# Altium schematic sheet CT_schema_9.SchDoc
size 274 x 160 mm
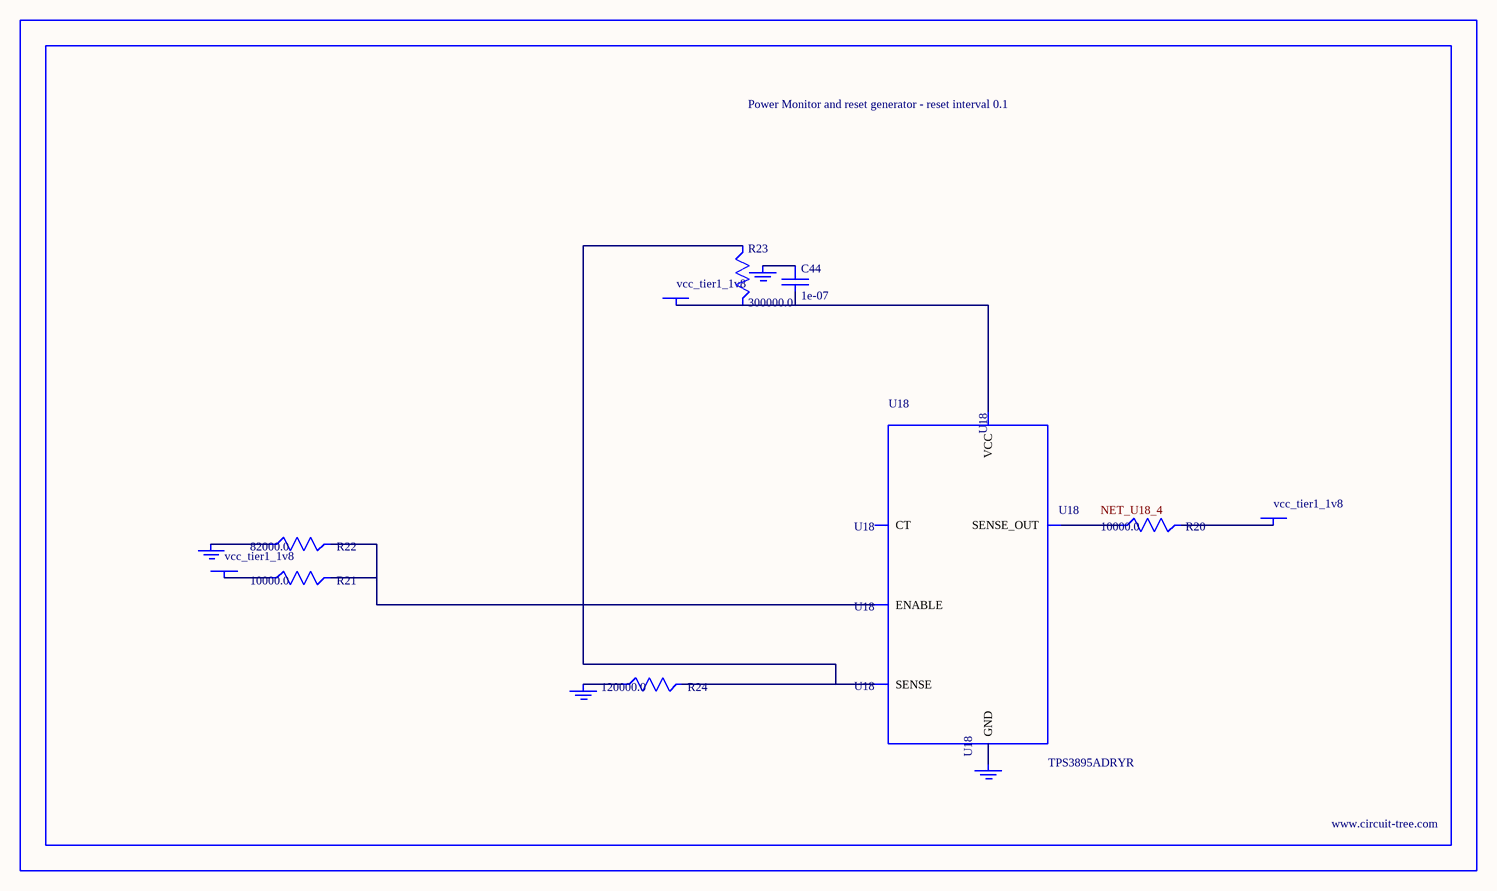
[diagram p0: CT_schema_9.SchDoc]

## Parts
BORDER8  (no value)
C44  1e-07  [C0402]
GND_INSTANCE_8_0  (no value)
GND_INSTANCE_8_1  (no value)
GND_INSTANCE_8_2  (no value)
GND_INSTANCE_8_3  (no value)
POWER_INSTANCE_8_0  vcc_tier1_1v8
POWER_INSTANCE_8_1  vcc_tier1_1v8
POWER_INSTANCE_8_2  vcc_tier1_1v8
R20  10000.0  [R0603]
R21  10000.0  [R0603]
R22  82000.0  [R0603]
R23  300000.0  [R0603]
R24  120000.0  [R0603]
U18  TPS3895ADRYR  [SON-6]

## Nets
NetC44_1: C44.1 GND_INSTANCE_8_2.0(GND)
NetC44_2: C44.2 POWER_INSTANCE_8_2.0(PWR) R23.2 U18.6(VCC)
NetGND_INSTANCE_8_0_0: GND_INSTANCE_8_0.0(GND) R22.1
NetGND_INSTANCE_8_1_0: GND_INSTANCE_8_1.0(GND) R24.1
NetGND_INSTANCE_8_3_0: GND_INSTANCE_8_3.0(GND) U18.2(GND)
NetPOWER_INSTANCE_8_0_0: POWER_INSTANCE_8_0.0(PWR) R21.1
NetPOWER_INSTANCE_8_1_0: POWER_INSTANCE_8_1.0(PWR) R20.2
NetR20_1: R20.1 U18.4(SENSE_OUT)
NetR21_2: R21.2 R22.2 U18.1(ENABLE)
NetR23_1: R23.1 R24.2 U18.3(SENSE)

Not connected (* = marked no-connect by the designer): U18 5(CT)

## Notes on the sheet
- Labels drawn without touching a wire or pin: NET_U18_4

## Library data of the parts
BORDER8 = BORDER_PAGE8
C44 = C0402C104K3RACTU
GND_INSTANCE_8_0-GND_INSTANCE_8_3 = GND
POWER_INSTANCE_8_0-POWER_INSTANCE_8_2 = PWR
R20 R21 = RC0603JR-0710KL
R22 = RC0603JR-0782KL
R23 = RC0603JR-07300KL
R24 = RC0603JR-07120KL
